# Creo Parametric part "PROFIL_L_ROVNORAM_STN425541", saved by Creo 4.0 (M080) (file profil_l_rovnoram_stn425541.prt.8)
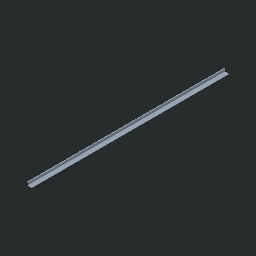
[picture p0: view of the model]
Units: millimeter Kilogram Sec (mmKs); MM, KILOGRAM, SECS
Materials in the file: OCEL_N

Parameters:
  MFG_WP_MATERIAL = "OCEL"
  NAZOV = "PROFIL_L_ROVNORAM_STN425541"
  NORMA = "STN 42 5541"
  PTC_MATERIAL_NAME = "OCEL_N"

Other parameters: HMOTNOST, HUSTOTA, D5, D2, D6

Created from: L_ROVNORAM.PRT

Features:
  1. datum plane "DTM1"

Layers: 1, 2, 3, 4, 5, 6, 7, 8, 9, 10, 11, 12, 13, 14, 15, 16, 17, 18, 19, 20, 21, 22, 23, 24, 25, 26, 27, 28, 29, 30, 31, 32

Family table entries: GENERIC, PROFIL_L_20X20X3, PROFIL_L_ROVNORAM_STN425541, value(d_val), value(i_val), PROFIL_L_25X25X3, PROFIL_L_ROVNORAM_STN425541, !/9, PROFIL_L_30X30X3, PROFIL_L_ROVNORAM_STN425541, !/>, PROFIL_L_35X35X4, PROFIL_L_ROVNORAM_STN425541, PROFIL_L_40X30X5, PROFIL_L_ROVNORAM_STN425541, !/D, PROFIL_L_45X45X5, PROFIL_L_ROVNORAM_STN425541, PROFIL_L_50X50X5, PROFIL_L_ROVNORAM_STN425541, !/I, PROFIL_L_55X55X5, PROFIL_L_ROVNORAM_STN425541, 2/ , PROFIL_L_60X60X6, PROFIL_L_ROVNORAM_STN425541, !/N, 2/ , PROFIL_L_70X70X6, PROFIL_L_ROVNORAM_STN425541, 2/$, PROFIL_L_70X70X8, PROFIL_L_ROVNORAM_STN425541, 2/ , 2/$, PROFIL_L_80X80X6, PROFIL_L_ROVNORAM_STN425541, !/T, 2/$, PROFIL_L_80X80X8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

Surfaces: 8 plane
